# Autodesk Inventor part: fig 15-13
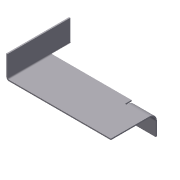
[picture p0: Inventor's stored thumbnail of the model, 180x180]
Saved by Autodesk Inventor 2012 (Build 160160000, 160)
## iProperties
Shininess: 77.0
Angle Display Precision: 2
Document Length Units: 11269
Document Angle Units: 11279
Document Time Units: 11290
Document Mass Units: 11283
Document Length Units Precision: 3
Document Angle Units Precision: 2
Created: 2002-04
Part Number: fig 15-13
Material: Aluminum-6061
Document SubType Name: Sheet Metal
Density: 1 g/cm^3
Sheet Metal Rule: Default
Density: 0.0
Volumn: 0.0
Area: 0.0
PropertySet Name: Model Information
Control State: 0
Master: False
Checked Out: False
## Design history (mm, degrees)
node "Face1"
  sketch "Sketch1"
    geometry: L1 (-49.559, 19.574)-(-49.559, -30.426); L2 (-49.559, -30.426)-(50.441, -30.426); L3 (50.441, -30.426)-(50.441, 19.574); L4 (50.441, 19.574)-(32.941, 19.574); L5 (32.941, 19.574)-(32.941, 4.574); L6 (32.941, 4.574)-(-32.059, 4.574); L7 (-32.059, 4.574)-(-32.059, 19.574); L8 (-32.059, 19.574)-(-49.559, 19.574)
    constraints: 16 end point, 6 parallel, 2 equal length, 1 perpendicular, 1 vertical
    dimensions: "d0" = 100 distance of L1.end L2.end; "d1" = 65 distance of L5.end L6.end; "d2" = 15 distance of L6.end L7.end; "d3" = 50 distance of L1.start L1.end
sketch "Sketch2"
  geometry: L1 (100, 0)-(0, 0) reference; L2 (17.5, 50)-(17.5, 35) reference; L3 (82.5, 50)-(82.5, 0)
  constraints: 2 end point, 1 parallel, 1 point on line
sketch "Sketch3"
  geometry: L1 (81.369, -50)-(0, -50) reference; L2 (17.5, 0)-(17.5, -50)
  constraints: 2 end point, 1 perpendicular, 1 point on line
feature "Fold2" sketch "Sketch3" dims "d8" = 1 (= BendRadius), "d9" = 90 deg, "d10" = 1 (= BendRadius), "d14" = 1 (= BendReliefWidth), "d15" = 0.5 (= BendReliefDepth), "d16" = 2 (= MinimumRemnant), "SeamGap" = 0.01, "Thickness" = 1
sketch "Sketch4"
  geometry: L1 (17.5, 0)-(17.5, -50) reference; L2 (-63.869, -15)-(0, -15) reference; L3 (0, -15)-(17.5, -15)
  constraints: 2 end point, 1 collinear, 1 point on line
feature "Fold3" sketch "Sketch4" dims "d11" = 1 (= BendRadius), "d12" = 90 deg, "d13" = 5, "d17" = 1 (= BendReliefWidth), "d18" = 1, "d19" = 2 (= MinimumRemnant), "SeamGap" = 0.01, "Thickness" = 1
body "Solid1"
face "Plate1" dims "Thickness" = 1
other parameters: "BendRadius" = 1 (= Thickness), "BendReliefWidth" = 1 (= Thickness), "BendReliefDepth" = 0.5 (= 0.5 x Thickness), "CornerReliefSize" = 4 (= 4 x Thickness), "MinimumRemnant" = 2 (= 2 x Thickness), "TransitionRadius" = 1 (= BendRadius), "d4" = 1 (= BendRadius), "JacobiRadiusSize" = 1 (= Thickness), "GapSize" = 1 (= Thickness)
